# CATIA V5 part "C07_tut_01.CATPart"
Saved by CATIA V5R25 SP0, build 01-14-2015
Part number: Part1
Bounding box of the stored display mesh (mm): x -150 to 150, y -150 to 150, z -127.71 to 0
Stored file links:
  E:\ashutosh\Academics\Catia\CATIA V5-6R2013_partfiles\Tutorials_ver_2\C07_tut_01.CATPart
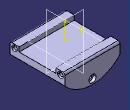
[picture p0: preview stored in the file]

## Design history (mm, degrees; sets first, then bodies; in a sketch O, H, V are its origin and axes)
Body1 (main body)
  Sketch1 on zx-plane, origin (0, 0, 0), H (-1, 0, 0), V (0, 0, 1)
    point P1 (-150, 0)
    line L1 (-150, 0) -> (150, 0)
    point P2 (150, 0)
    line L2 (150, 0) -> (150, -60)
    point P3 (150, -60)
    point P4 (-150, -60)
    point P5 (-150, 0)
    line L3 (-150, 0) -> (-150, -60)
    arc A1 centre (0, 72.2876) radius 200 from (150, -60) to (-150, -60) cw
    point P7 (0, -127.7124)
    length L1 = 300
    length L2 = 60
    radius A1 = 200
    horizontal: L1 H
    vertical: L2 V
    symmetry: P1 P2 V, P3 P4 V, P2 P5 V, L2 L3 V
    coincidence: L1 H, A1 P7, P7 V, P1 P5
  Pad1: profile Sketch1, direction (0, 1, 0), length 150, mirrored extent
  Sketch2 on yz-plane, origin (0, 0, 0), H (0, 1, 0), V (0, 0, 1)
    line L1 (100, 0) -> (-100, 0)
    reference projected line E1 (-150, 0) -> (150, 0) from edge [face of Pad1 from Sketch1.L3 | face of Pad1 from Sketch1.L1]
    line L2 (-100, 0) -> (-100, -25)
    line L3 (-100, -25) -> (100, -25)
    line L4 (100, -25) -> (100, 0)
    length L1 = 200
    length L4 = 25
    horizontal: L1 H, L3 H
    coincidence: L1 E1
    vertical: L2 V, L4 V
  Pocket1: profile Sketch2, direction (-1, 0, 0), length 150, mirrored extent
  Fillet1: radius 10, on edge [start face of Pad1 | face of Pad1 from Sketch1.L1]; edge [face of Pad1 from Sketch1.L1 | end face of Pad1]
  Sketch3 on yz-plane, origin (0, 0, 0), H (0, 1, 0), V (0, 0, 1)
    point P1 (-125, -20)
    point P2 (125, -20)
    reference projected line E1 (150, 0) -> (150, -60) from edge [face of Pad1 from Sketch1.L3 | end face of Pad1]
    reference projected line E2 (-150, 0) -> (150, 0) from edge [face of Pad1 from Sketch1.L3 | face of Pad1 from Sketch1.L1]
    distance P2 E1 = 25
    distance P2 E2 = 20
    symmetry: P1 P2 V
  Sketch4 on face of Pad1 from Sketch1.L3, origin (150, 125, -20), H (0, 1, 0), V (0, 0, 1)
    point P1 (0, 0)
    reference projected point E1 (0, 0) from Sketch3.P2
    coincidence: E1 P1
  Hole1: placed by Sketch4, at (150, 125, -20) direction (-1, 0, 0), diameter 20, through (limit type 3), countersink depth 5, countersink angle 90
  Sketch5 on face of Pad1 from Sketch1.L3, origin (150, -125, -20), H (0, 1, 0), V (0, 0, 1)
    point P1 (0, 0)
    reference projected point E1 (0, 0) from Sketch3.P1
    coincidence: E1 P1
  Hole2: placed by Sketch5, at (150, -125, -20) direction (-1, 0, 0), diameter 20, through (limit type 3), countersink depth 5, countersink angle 90
  Sketch6 on zx-plane, origin (0, 0, 0), H (-1, 0, 0), V (0, 0, 1)
    point P1 (0, -100)
    distance P1 H = 100
    coincidence: P1 V
  Sketch7 on end face of Pad1, origin (0, 150, -100), H (1, 0, 0), V (0, 0, -1)
    point P1 (0, 0)
    reference projected point E1 (0, 0) from Sketch6.P1
    coincidence: E1 P1
  Hole3: placed by Sketch7, at (0, 150, -100) direction (0, -1, 0), diameter 20, through (limit type 3), counterbore diameter 40, counterbore depth 15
